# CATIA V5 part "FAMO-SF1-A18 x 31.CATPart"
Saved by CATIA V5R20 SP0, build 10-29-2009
Part number: FAMO-SF1-A18 x 31
Definition: NONE
Nomenclature: FAMO-SF1-A18 x 31
Source: Unknown
Description: FAMO-SF1-A18 x 31
Bounding box of the stored display mesh (mm): x -13 to 18, y -17 to 17, z -17 to 17
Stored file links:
  C:\Users\Utente\Desktop\IO LAVORO\3D X SITO CF\X SITO\FAMO\FAMO-SF1-A18 x 31.CATPart
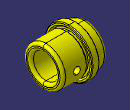
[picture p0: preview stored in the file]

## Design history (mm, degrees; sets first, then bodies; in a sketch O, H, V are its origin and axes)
Body1 "FAMO-SF1-A18 x 31" (main body)
  Solid1: solid without history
